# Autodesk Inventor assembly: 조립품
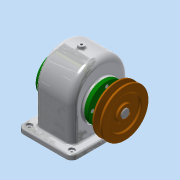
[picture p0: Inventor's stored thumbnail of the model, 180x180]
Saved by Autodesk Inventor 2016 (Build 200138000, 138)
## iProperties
Created: 2018-11
Part Number: 조립품
Material: 일반
Document SubType Name: Assembly
Designer: user
Author: user
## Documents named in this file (14)
- C:\Users\user\Desktop\481111V1009\조립품.iam
- C:\Users\user\Desktop\481111V1009\V-벨트풀리.ipt
- C:\Users\user\Desktop\481111V1009\뒤커버.ipt
- C:\Users\user\Desktop\481111V1009\멈춤나사 M4.ipt
- C:\Users\user\Desktop\481111V1009\베어링 6203.ipt
- C:\Users\user\Desktop\481111V1009\본체.ipt
- C:\Users\user\Desktop\481111V1009\볼트 M4.ipt
- C:\Users\user\Desktop\481111V1009\부시.ipt
- C:\Users\user\Desktop\481111V1009\스퍼기어.ipt
- C:\Users\user\Desktop\481111V1009\앞커버.ipt
- C:\Users\user\Desktop\481111V1009\오일 실 28 40 8.ipt
- C:\Users\user\Desktop\481111V1009\축.ipt
- C:\Users\user\Desktop\481111V1009\키 5x5x18.ipt
- C:\Users\user\Desktop\481111V1009\키 6x6x22.ipt
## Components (1 placed, 1 different names)
1. V-벨트풀리:1
